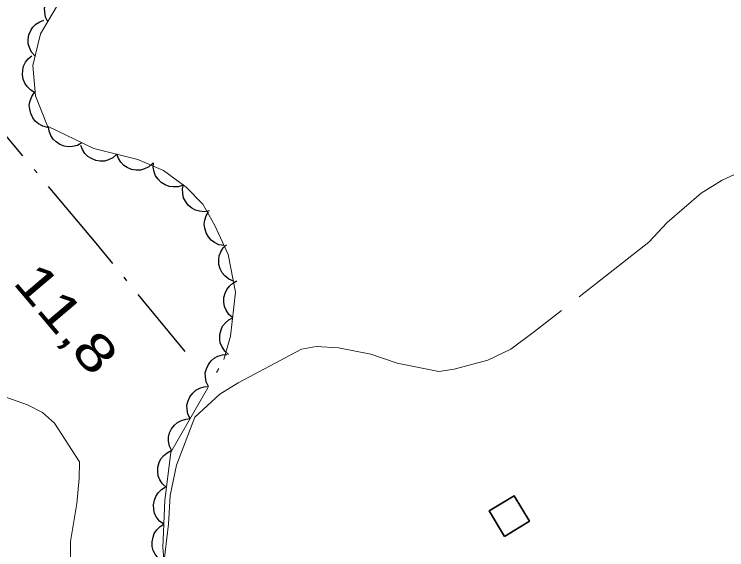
# Model space of a CAD drawing. Extents: x 386081 to 389416, y 5130568 to 5134082.
# Drawn here: x 387180.4 to 387238.2, y 5131828.9 to 5131872.3 of the extents above; entities that cross this region are included whole.
import ezdxf

# ---------------------------------------------------------------- set-up
doc = ezdxf.new("R2010")
doc.units = 0
doc.header["$LTSCALE"] = 1.2
doc.linetypes.add('DOT_DASHED', pattern=[7.7, 5, -1.2, 0.3, -1.2])
doc.linetypes.add('LONG_DASHED', pattern=[7.5, 6, -1.5])
for name, color, linetype, lineweight in [('2', 7, 'Continuous', 13), ('3', 7, 'Continuous', 140), ('31', 7, 'Continuous', 70), ('41', 7, 'DOT_DASHED', 25), ('44', 7, 'Continuous', 25)]:
    doc.layers.add(name, color=color, linetype=linetype, lineweight=lineweight)

msp = doc.modelspace()

# ---------------------------------------------------------------- linework, layer by layer
at = {"layer": '2', "linetype": 'LONG_DASHED'}
msp.add_lwpolyline([(387240.97, 5131860.38), (387237.8, 5131858.9), (387236.08, 5131857.84), (387233.34, 5131855.48), (387231.85, 5131853.88), (387222.57, 5131846.62), (387220.65, 5131845.2), (387218.77, 5131844.32), (387216.05, 5131843.58), (387214.8, 5131843.4), (387211.42, 5131844.07), (387209.3, 5131844.8), (387206.66, 5131845.32), (387204.87, 5131845.42), (387203.68, 5131845.21), (387198.54, 5131842.46), (387197.04, 5131841.55), (387195.01, 5131839.7), (387193.53, 5131835.8), (387193.02, 5131833.35), (387192.89, 5131831.02), (387192.37, 5131826.9)], dxfattribs=at)
at = {"layer": '2'}
msp.add_lwpolyline([(387179.22, 5131841.46), (387181.43, 5131840.7), (387182.66, 5131840.08), (387183.64, 5131839.21), (387185.65, 5131836.06), (387185.64, 5131834.71), (387185.44, 5131832.68), (387184.93, 5131829.61), (387184.9, 5131825.68)], dxfattribs=at)
at = {"layer": '31', "lineweight": 35}
msp.add_lwpolyline([(387220.14, 5131830.03), (387218.89, 5131832.09), (387220.91, 5131833.32), (387222.16, 5131831.26)], close=True, dxfattribs=at)
at = {"layer": '41'}
msp.add_lwpolyline([(387194.22, 5131845), (387187.01, 5131853.79), (387178.46, 5131863.95), (387171.51, 5131855.89), (387167.54, 5131851.99), (387163.86, 5131854.24)], dxfattribs=at)
at = {"layer": '44'}
for points in [[(387183.08, 5131871.74), (387182.9, 5131872.12), (387182.84, 5131872.52), (387182.83, 5131872.85), (387182.93, 5131873.19), (387183.09, 5131873.53), (387183.33, 5131873.82), (387183.57, 5131874.04), (387183.89, 5131874.2), (387184.24, 5131874.31), (387184.6, 5131874.33)], [(387182.05, 5131868.96), (387181.77, 5131869.27), (387181.6, 5131869.64), (387181.5, 5131869.95), (387181.49, 5131870.3), (387181.55, 5131870.67), (387181.7, 5131871.02), (387181.87, 5131871.3), (387182.12, 5131871.54), (387182.43, 5131871.74), (387182.77, 5131871.87)], [(387182.07, 5131865.99), (387181.7, 5131866.19), (387181.42, 5131866.48), (387181.22, 5131866.75), (387181.1, 5131867.08), (387181.03, 5131867.44), (387181.06, 5131867.82), (387181.12, 5131868.14), (387181.28, 5131868.45), (387181.51, 5131868.75), (387181.79, 5131868.98)], [(387183.09, 5131863.18), (387182.69, 5131863.27), (387182.33, 5131863.47), (387182.07, 5131863.67), (387181.86, 5131863.95), (387181.7, 5131864.29), (387181.62, 5131864.66), (387181.58, 5131864.99), (387181.66, 5131865.33), (387181.79, 5131865.68), (387181.99, 5131865.97)], [(387185.85, 5131861.93), (387185.49, 5131861.72), (387185.09, 5131861.62), (387184.76, 5131861.59), (387184.42, 5131861.66), (387184.07, 5131861.79), (387183.76, 5131862.01), (387183.51, 5131862.23), (387183.33, 5131862.53), (387183.2, 5131862.87), (387183.15, 5131863.23)], [(387188.68, 5131861), (387188.37, 5131860.72), (387188.01, 5131860.54), (387187.69, 5131860.45), (387187.34, 5131860.44), (387186.97, 5131860.5), (387186.62, 5131860.65), (387186.34, 5131860.81), (387186.1, 5131861.07), (387185.9, 5131861.38), (387185.77, 5131861.72)], [(387191.6, 5131860.27), (387191.29, 5131859.99), (387190.92, 5131859.82), (387190.6, 5131859.72), (387190.25, 5131859.71), (387189.88, 5131859.77), (387189.53, 5131859.93), (387189.25, 5131860.09), (387189.01, 5131860.35), (387188.81, 5131860.66), (387188.68, 5131861)], [(387194.06, 5131858.5), (387193.67, 5131858.37), (387193.26, 5131858.35), (387192.93, 5131858.38), (387192.61, 5131858.51), (387192.29, 5131858.71), (387192.03, 5131858.98), (387191.83, 5131859.24), (387191.71, 5131859.57), (387191.64, 5131859.94), (387191.66, 5131860.3)], [(387196.21, 5131856.41), (387195.79, 5131856.33), (387195.39, 5131856.38), (387195.07, 5131856.46), (387194.77, 5131856.63), (387194.48, 5131856.87), (387194.26, 5131857.19), (387194.1, 5131857.47), (387194.04, 5131857.82), (387194.02, 5131858.19), (387194.09, 5131858.54)], [(387197.38, 5131853.61), (387196.97, 5131853.67), (387196.61, 5131853.85), (387196.33, 5131854.03), (387196.11, 5131854.31), (387195.92, 5131854.63), (387195.82, 5131855), (387195.77, 5131855.32), (387195.82, 5131855.67), (387195.94, 5131856.02), (387196.12, 5131856.33)], [(387198.14, 5131850.72), (387197.76, 5131850.88), (387197.45, 5131851.15), (387197.22, 5131851.39), (387197.07, 5131851.71), (387196.97, 5131852.06), (387196.96, 5131852.44), (387196.98, 5131852.77), (387197.12, 5131853.09), (387197.31, 5131853.41), (387197.57, 5131853.67)], [(387198.09, 5131847.75), (387197.77, 5131848.02), (387197.55, 5131848.36), (387197.41, 5131848.66), (387197.36, 5131849.01), (387197.37, 5131849.38), (387197.48, 5131849.75), (387197.6, 5131850.05), (387197.82, 5131850.32), (387198.1, 5131850.56), (387198.42, 5131850.73)], [(387197.75, 5131844.77), (387197.44, 5131845.04), (387197.22, 5131845.38), (387197.08, 5131845.68), (387197.03, 5131846.03), (387197.04, 5131846.4), (387197.14, 5131846.77), (387197.26, 5131847.07), (387197.49, 5131847.34), (387197.77, 5131847.58), (387198.09, 5131847.75)], [(387196.12, 5131842.17), (387195.94, 5131842.55), (387195.87, 5131842.95), (387195.86, 5131843.28), (387195.95, 5131843.62), (387196.11, 5131843.95), (387196.35, 5131844.25), (387196.58, 5131844.48), (387196.89, 5131844.64), (387197.25, 5131844.75), (387197.61, 5131844.78)], [(387194.63, 5131839.57), (387194.45, 5131839.94), (387194.38, 5131840.34), (387194.37, 5131840.67), (387194.46, 5131841.01), (387194.62, 5131841.35), (387194.86, 5131841.64), (387195.09, 5131841.87), (387195.41, 5131842.03), (387195.76, 5131842.14), (387196.12, 5131842.17)], [(387193.14, 5131836.96), (387192.96, 5131837.34), (387192.89, 5131837.74), (387192.88, 5131838.07), (387192.97, 5131838.41), (387193.13, 5131838.74), (387193.37, 5131839.04), (387193.6, 5131839.27), (387193.92, 5131839.43), (387194.27, 5131839.54), (387194.63, 5131839.57)], [(387192.71, 5131834), (387192.4, 5131834.28), (387192.18, 5131834.62), (387192.05, 5131834.93), (387192, 5131835.28), (387192.02, 5131835.64), (387192.13, 5131836.01), (387192.26, 5131836.31), (387192.49, 5131836.58), (387192.77, 5131836.81), (387193.1, 5131836.98)], [(387192.49, 5131831.01), (387192.16, 5131831.26), (387191.91, 5131831.59), (387191.75, 5131831.87), (387191.68, 5131832.22), (387191.66, 5131832.59), (387191.74, 5131832.96), (387191.84, 5131833.27), (387192.04, 5131833.56), (387192.31, 5131833.82), (387192.61, 5131834.01)], [(387192.38, 5131828.01), (387192.04, 5131828.26), (387191.8, 5131828.59), (387191.64, 5131828.88), (387191.56, 5131829.22), (387191.54, 5131829.59), (387191.62, 5131829.96), (387191.72, 5131830.27), (387191.93, 5131830.56), (387192.19, 5131830.82), (387192.49, 5131831.01)]]:
    msp.add_lwpolyline(points, dxfattribs=at)
at = {"layer": '44', "linetype": 'DOT_DASHED', "lineweight": 13}
msp.add_lwpolyline([(387192.65, 5131826.42), (387192.42, 5131829.13), (387192.57, 5131832.93), (387193.08, 5131836.85), (387197.37, 5131844.36), (387197.92, 5131846.25), (387198.32, 5131849.81), (387197.72, 5131852.88), (387196.63, 5131855.23), (387195.66, 5131856.96), (387194.31, 5131858.32), (387192.47, 5131859.69), (387190.39, 5131860.57), (387186.82, 5131861.46), (387183.06, 5131863.27), (387182.09, 5131865.73), (387181.86, 5131868.19), (387182.5, 5131870.77), (387183.87, 5131873.09)], dxfattribs=at)

# ---------------------------------------------------------------- texts
at = {"layer": '3', "width": 1.3}
msp.add_text('11,8   ', height=3, rotation=310.294, dxfattribs=at).set_placement((387180.17, 5131850.59))

doc.saveas('drawing.dxf')
